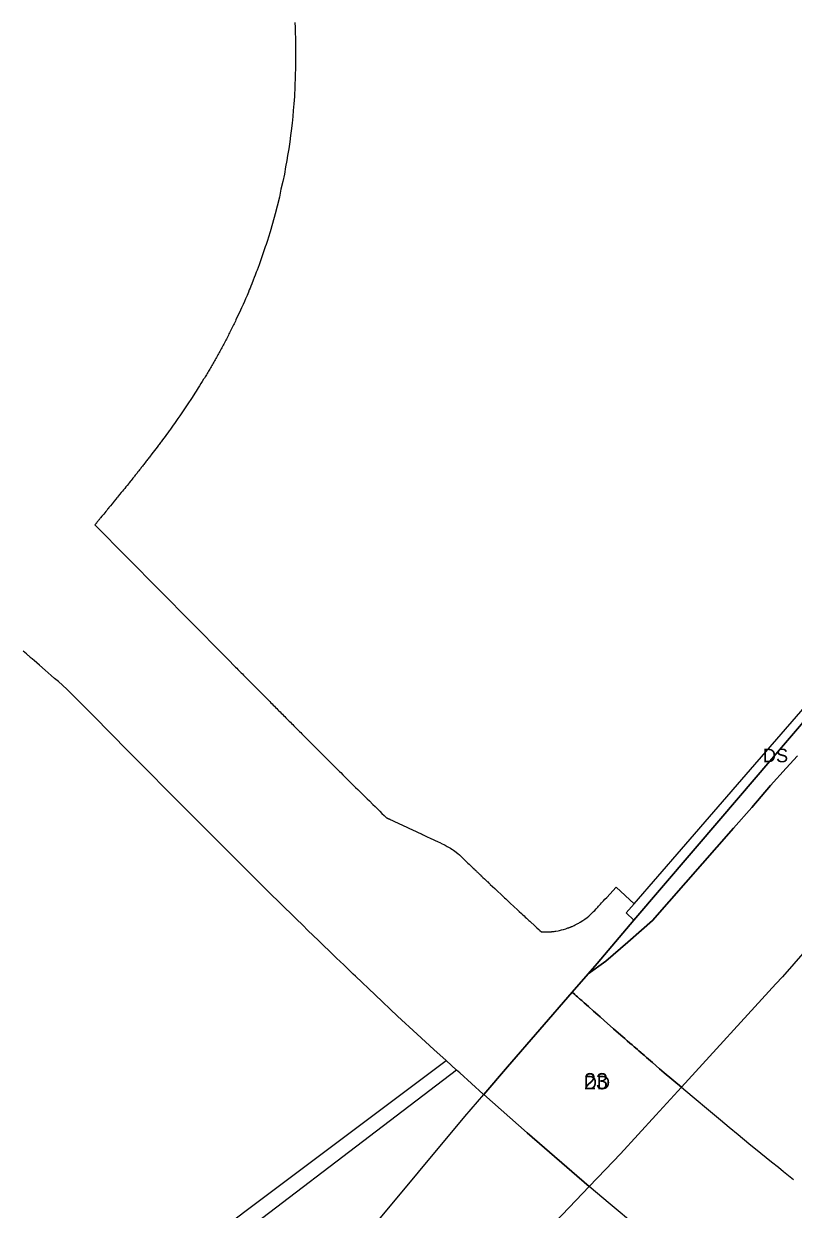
# Model space of a CAD drawing. Extents: x -537034 to -534353, y -1176562 to -1173176.
# Drawn here: x -536073.5 to -535789.3, y -1174862.1 to -1174424.3 of the extents above; entities that cross this region are included whole.
import ezdxf

# ---------------------------------------------------------------- set-up
doc = ezdxf.new("R2010")
doc.units = 0
for name, color, linetype in [('90320013', 7, 'Continuous'), ('90320023', 7, 'Continuous'), ('90330013', 7, 'Continuous'), ('90330023', 7, 'Continuous'), ('90390023', 7, 'Continuous'), ('ID_navrh', 7, 'Continuous')]:
    doc.layers.add(name, color=color, linetype=linetype)

msp = doc.modelspace()

# ---------------------------------------------------------------- linework, layer by layer
at = {"layer": '90320013'}
msp.add_lwpolyline([(-535848.15, -1174755.35), (-535850.97, -1174752.61), (-535848.1, -1174749.3), (-535830.53, -1174729.03), (-535805.04, -1174699.64), (-535782.42, -1174673.55), (-535753.14, -1174639.77), (-535750.85, -1174637.13), (-535749.98, -1174641.67), (-535765, -1174658.05), (-535771.01, -1174665.09), (-535791.35, -1174688.89), (-535816, -1174717.74)], close=True, dxfattribs=at)
msp.add_lwpolyline([(-536068.27, -1174920.24), (-535917.53, -1174807.16), (-535913.69, -1174810.62), (-536019.96, -1174891.69)], dxfattribs=at)
at = {"layer": '90320023'}
for points in [[(-535973.34, -1174423.76), (-535973.25, -1174425.67), (-535973.09, -1174431.51), (-535973.09, -1174440.09), (-535973.53, -1174451.08), (-535973.74, -1174453.87), (-535973.92, -1174456.32), (-535974.14, -1174458.55), (-535974.4, -1174460.96), (-535974.7, -1174463.8), (-535974.92, -1174465.59), (-535975.27, -1174467.86), (-535975.62, -1174470.51), (-535976.06, -1174472.91), (-535976.32, -1174474.79), (-535976.8, -1174477.15), (-535977.24, -1174479.82), (-535977.81, -1174482.49), (-535978.51, -1174485.37), (-535979.03, -1174488.26), (-535979.91, -1174491.58), (-535980.61, -1174494.47), (-535981.66, -1174498.05), (-535982.53, -1174501.11), (-535983.14, -1174503.12), (-535983.51, -1174504.29), (-535983.98, -1174505.75), (-535984.29, -1174506.7), (-535986.55, -1174513.28), (-535987.3, -1174515.29), (-535987.6, -1174516.05), (-535988.02, -1174517.16), (-535988.33, -1174518), (-535988.71, -1174518.94), (-535989.24, -1174520.28), (-535989.6, -1174521.18), (-535989.89, -1174521.88), (-535990.18, -1174522.58), (-535990.5, -1174523.37), (-535991.02, -1174524.56), (-535991.54, -1174525.8), (-535991.98, -1174526.78), (-535992.48, -1174527.97), (-535993.05, -1174529.17), (-535993.4, -1174530.02), (-535995.11, -1174533.63), (-535995.31, -1174534.06), (-535995.54, -1174534.54), (-535995.78, -1174535.02), (-535996.01, -1174535.51), (-535996.25, -1174535.98), (-535996.48, -1174536.46), (-535996.72, -1174536.94), (-535996.96, -1174537.41), (-535997.2, -1174537.89), (-535997.44, -1174538.36), (-535997.68, -1174538.83), (-535997.91, -1174539.3), (-535998.15, -1174539.76), (-535998.4, -1174540.23), (-535998.64, -1174540.69), (-535998.88, -1174541.16), (-535999.12, -1174541.62), (-535999.36, -1174542.08), (-535999.61, -1174542.53), (-535999.85, -1174542.99), (-536000.09, -1174543.44), (-536000.34, -1174543.89), (-536000.58, -1174544.35), (-536000.83, -1174544.8), (-536001.07, -1174545.24), (-536001.32, -1174545.69), (-536001.56, -1174546.13), (-536001.81, -1174546.58), (-536002.06, -1174547.02), (-536002.3, -1174547.46), (-536002.55, -1174547.9), (-536002.8, -1174548.33), (-536003.05, -1174548.77), (-536003.3, -1174549.2), (-536003.54, -1174549.64), (-536003.79, -1174550.07), (-536004.04, -1174550.49), (-536004.29, -1174550.92), (-536004.54, -1174551.35), (-536004.79, -1174551.77), (-536005.04, -1174552.2), (-536005.29, -1174552.62), (-536005.54, -1174553.04), (-536005.79, -1174553.46), (-536006.04, -1174553.87), (-536006.54, -1174554.7), (-536006.79, -1174555.12), (-536007.04, -1174555.53), (-536007.55, -1174556.35), (-536007.8, -1174556.75), (-536008.05, -1174557.16), (-536008.55, -1174557.96), (-536009.06, -1174558.76), (-536009.81, -1174559.95), (-536010.32, -1174560.74), (-536011.32, -1174562.29), (-536012.08, -1174563.45), (-536012.33, -1174563.83), (-536012.58, -1174564.21), (-536012.83, -1174564.58), (-536013.09, -1174564.96), (-536013.34, -1174565.34), (-536013.59, -1174565.71), (-536013.84, -1174566.08), (-536014.09, -1174566.45), (-536014.34, -1174566.82), (-536014.59, -1174567.19), (-536014.84, -1174567.56), (-536015.09, -1174567.93), (-536015.34, -1174568.29), (-536015.59, -1174568.65), (-536015.84, -1174569.02), (-536016.59, -1174570.09), (-536017.59, -1174571.51), (-536018.58, -1174572.91), (-536019.57, -1174574.29), (-536019.82, -1174574.63), (-536020.31, -1174575.3), (-536020.8, -1174575.98), (-536021.29, -1174576.65), (-536021.77, -1174577.31), (-536022.26, -1174577.97), (-536022.5, -1174578.29), (-536022.75, -1174578.62), (-536022.99, -1174578.95), (-536023.23, -1174579.27), (-536023.47, -1174579.59), (-536023.71, -1174579.91), (-536023.98, -1174580.27), (-536024.22, -1174580.59), (-536024.7, -1174581.22), (-536025.17, -1174581.85), (-536025.65, -1174582.48), (-536026.12, -1174583.09), (-536027.06, -1174584.32), (-536027.3, -1174584.62), (-536027.53, -1174584.92), (-536027.76, -1174585.22), (-536027.99, -1174585.52), (-536028.23, -1174585.82), (-536028.46, -1174586.12), (-536028.92, -1174586.71), (-536029.15, -1174587), (-536029.38, -1174587.3), (-536029.61, -1174587.59), (-536029.84, -1174587.88), (-536030.06, -1174588.17), (-536030.29, -1174588.46), (-536030.52, -1174588.75), (-536030.74, -1174589.03), (-536030.97, -1174589.32), (-536031.19, -1174589.6), (-536031.42, -1174589.88), (-536031.64, -1174590.17), (-536031.86, -1174590.45), (-536032.09, -1174590.73), (-536032.31, -1174591.01), (-536032.53, -1174591.28), (-536032.75, -1174591.56), (-536032.97, -1174591.84), (-536033.19, -1174592.11), (-536033.41, -1174592.38), (-536033.85, -1174592.93), (-536034.06, -1174593.2), (-536034.5, -1174593.74), (-536034.71, -1174594), (-536035.35, -1174594.8), (-536035.78, -1174595.32), (-536036.2, -1174595.85), (-536036.62, -1174596.36), (-536037.04, -1174596.88), (-536037.45, -1174597.39), (-536038.07, -1174598.14), (-536038.47, -1174598.64), (-536038.88, -1174599.14), (-536039.08, -1174599.38), (-536039.48, -1174599.87), (-536040.07, -1174600.6), (-536040.47, -1174601.08), (-536040.86, -1174601.56), (-536041.44, -1174602.27), (-536042.01, -1174602.96), (-536042.01, -1174602.97), (-536042.02, -1174602.97), (-536042.02, -1174602.98), (-536042.03, -1174602.99), (-536042.03, -1174603), (-536042.04, -1174603), (-536042.04, -1174603.01), (-536042.05, -1174603.01), (-536042.06, -1174603.02), (-536042.06, -1174603.03), (-536042.07, -1174603.04), (-536042.07, -1174603.05), (-536042.08, -1174603.06), (-536042.09, -1174603.07), (-536042.1, -1174603.08), (-536042.11, -1174603.09), (-536042.12, -1174603.1), (-536042.13, -1174603.11), (-536042.13, -1174603.12), (-536042.14, -1174603.12), (-536042.14, -1174603.13), (-536042.15, -1174603.13), (-536042.15, -1174603.14), (-536042.16, -1174603.15), (-536042.17, -1174603.16), (-536042.17, -1174603.17), (-536042.21, -1174603.21), (-536042.25, -1174603.26), (-536042.29, -1174603.31), (-536042.36, -1174603.39), (-536042.4, -1174603.44), (-536042.45, -1174603.5), (-536042.5, -1174603.56), (-536042.66, -1174603.75), (-536042.86, -1174604.01), (-536043.05, -1174604.23), (-536043.2, -1174604.41), (-536043.54, -1174604.84), (-536043.96, -1174605.35), (-536044.61, -1174606.14), (-536045.11, -1174606.76), (-536045.23, -1174606.9), (-536045.38, -1174607.08), (-536045.5, -1174607.23), (-536045.65, -1174607.41), (-536045.73, -1174607.51), (-536045.86, -1174607.66), (-536045.99, -1174607.83), (-536046.08, -1174607.94), (-536046.31, -1174608.21), (-536046.49, -1174608.44), (-536046.66, -1174608.64), (-536046.81, -1174608.83), (-536046.92, -1174608.96), (-536047.02, -1174609.09), (-536047.12, -1174609.21), (-536047.2, -1174609.3), (-536047.23, -1174609.35), (-535999.47, -1174657.57), (-535998.21, -1174658.84), (-535997.36, -1174659.7), (-535996.1, -1174660.98), (-535995.25, -1174661.83), (-535994.83, -1174662.25), (-535994.41, -1174662.68), (-535993.56, -1174663.53), (-535993.14, -1174663.96), (-535992.72, -1174664.38), (-535992.3, -1174664.81), (-535991.46, -1174665.66), (-535990.61, -1174666.51), (-535989.77, -1174667.36), (-535988.92, -1174668.21), (-535988.08, -1174669.06), (-535987.24, -1174669.91), (-535986.39, -1174670.77), (-535985.55, -1174671.62), (-535984.71, -1174672.47), (-535983.86, -1174673.32), (-535983.02, -1174674.17), (-535982.6, -1174674.59), (-535982.18, -1174675.01), (-535981.75, -1174675.44), (-535981.33, -1174675.86), (-535980.91, -1174676.29), (-535980.49, -1174676.71), (-535980.07, -1174677.14), (-535979.65, -1174677.56), (-535979.22, -1174677.99), (-535978.8, -1174678.41), (-535978.38, -1174678.83), (-535977.96, -1174679.26), (-535977.54, -1174679.68), (-535977.12, -1174680.11), (-535976.69, -1174680.53), (-535976.27, -1174680.95), (-535975.85, -1174681.38), (-535975.43, -1174681.8), (-535975.01, -1174682.23), (-535974.59, -1174682.65), (-535974.16, -1174683.07), (-535973.74, -1174683.5), (-535973.32, -1174683.92), (-535972.9, -1174684.34), (-535972.48, -1174684.77), (-535972.05, -1174685.19), (-535971.63, -1174685.61), (-535971.21, -1174686.04), (-535970.79, -1174686.46), (-535970.37, -1174686.88), (-535969.95, -1174687.31), (-535968.26, -1174689), (-535966.15, -1174691.11), (-535964.04, -1174693.22), (-535962.35, -1174694.91), (-535961.08, -1174696.17), (-535959.81, -1174697.43), (-535958.54, -1174698.7), (-535957.7, -1174699.54), (-535956.85, -1174700.38), (-535956.43, -1174700.8), (-535955.58, -1174701.64), (-535954.74, -1174702.48), (-535953.89, -1174703.32), (-535953.05, -1174704.16), (-535951.78, -1174705.42), (-535950.93, -1174706.25), (-535950.08, -1174707.09), (-535949.24, -1174707.93), (-535947.97, -1174709.19), (-535946.69, -1174710.44), (-535945.85, -1174711.28), (-535944.57, -1174712.53), (-535943.73, -1174713.36), (-535942.88, -1174714.2), (-535942.03, -1174715.03), (-535941.18, -1174715.87), (-535940.33, -1174716.7), (-535939.63, -1174717.38), (-535939.46, -1174717.47), (-535939.4, -1174717.49), (-535939.36, -1174717.51), (-535939.34, -1174717.52), (-535939.3, -1174717.54), (-535939.26, -1174717.56), (-535939.23, -1174717.57), (-535939.21, -1174717.58), (-535939.19, -1174717.59), (-535939.13, -1174717.62), (-535939.08, -1174717.64), (-535939.04, -1174717.66), (-535939.02, -1174717.67), (-535938.98, -1174717.69), (-535938.96, -1174717.7), (-535938.94, -1174717.71), (-535938.9, -1174717.73), (-535938.87, -1174717.74), (-535938.86, -1174717.75), (-535938.84, -1174717.75), (-535938.83, -1174717.76), (-535938.82, -1174717.76), (-535938.82, -1174717.77), (-535938.81, -1174717.77), (-535938.8, -1174717.77), (-535938.79, -1174717.78), (-535938.78, -1174717.78), (-535938.77, -1174717.79), (-535938.76, -1174717.79), (-535938.75, -1174717.8), (-535938.73, -1174717.81), (-535938.72, -1174717.81), (-535938.71, -1174717.82), (-535938.69, -1174717.82), (-535938.68, -1174717.83), (-535938.66, -1174717.84), (-535938.65, -1174717.84), (-535938.64, -1174717.85), (-535938.62, -1174717.86), (-535938.6, -1174717.87), (-535938.55, -1174717.89), (-535938.54, -1174717.9), (-535938.52, -1174717.9), (-535938.51, -1174717.91), (-535938.5, -1174717.91), (-535938.44, -1174717.94), (-535938.41, -1174717.96), (-535938.37, -1174717.98), (-535938.22, -1174718.04), (-535938.15, -1174718.08), (-535937.86, -1174718.21), (-535937.55, -1174718.36), (-535937.31, -1174718.47), (-535936.55, -1174718.83), (-535933.61, -1174720.2), (-535929.65, -1174722.06), (-535928.75, -1174722.48), (-535927.61, -1174723.01), (-535926.64, -1174723.47), (-535926.16, -1174723.69), (-535925.76, -1174723.88), (-535924.52, -1174724.47), (-535923.38, -1174725), (-535920.41, -1174726.38), (-535919.82, -1174726.66), (-535918.98, -1174727.06), (-535918.39, -1174727.35), (-535917.84, -1174727.62), (-535917.44, -1174727.85), (-535917.08, -1174728.04), (-535916.65, -1174728.29), (-535916.39, -1174728.44), (-535916.15, -1174728.59), (-535915.89, -1174728.76), (-535915.44, -1174729.05), (-535915.14, -1174729.25), (-535914.82, -1174729.47), (-535914.32, -1174729.83), (-535913.2, -1174730.67), (-535912.57, -1174731.22), (-535912.23, -1174731.52), (-535911.54, -1174732.14), (-535910.84, -1174732.83), (-535910.5, -1174733.2), (-535910.11, -1174733.61), (-535909.9, -1174733.82), (-535909.47, -1174734.22), (-535909.04, -1174734.63), (-535908.62, -1174735.04), (-535907.53, -1174736.06), (-535907.07, -1174736.51), (-535906.92, -1174736.65), (-535906.87, -1174736.69), (-535906.82, -1174736.74), (-535906.79, -1174736.77), (-535906.77, -1174736.79), (-535906.75, -1174736.81), (-535906.73, -1174736.82), (-535906.72, -1174736.83), (-535906.71, -1174736.84), (-535906.7, -1174736.85), (-535906.7, -1174736.86), (-535906.69, -1174736.86), (-535906.69, -1174736.87), (-535906.68, -1174736.87), (-535906.68, -1174736.88), (-535906.67, -1174736.88), (-535906.67, -1174736.89), (-535906.66, -1174736.89), (-535906.65, -1174736.9), (-535906.65, -1174736.91), (-535906.64, -1174736.91), (-535906.63, -1174736.92), (-535906.63, -1174736.93), (-535906.62, -1174736.93), (-535906.61, -1174736.94), (-535906.6, -1174736.95), (-535906.42, -1174737.13), (-535906.29, -1174737.24), (-535906.1, -1174737.42), (-535905.96, -1174737.56), (-535905.29, -1174738.19), (-535905.1, -1174738.37), (-535904.94, -1174738.52), (-535904.85, -1174738.61), (-535904.72, -1174738.73), (-535904.63, -1174738.82), (-535904.33, -1174739.1), (-535904.15, -1174739.27), (-535903.9, -1174739.5), (-535903.35, -1174740.03), (-535903.18, -1174740.18), (-535902.97, -1174740.39), (-535902.75, -1174740.59), (-535902.57, -1174740.76), (-535902.29, -1174741.02), (-535902.13, -1174741.17), (-535901.84, -1174741.45), (-535901.63, -1174741.64), (-535901.38, -1174741.88), (-535901.19, -1174742.07), (-535900.31, -1174742.88), (-535899.5, -1174743.65), (-535898.36, -1174744.72), (-535897.3, -1174745.7), (-535896.56, -1174746.4), (-535896.24, -1174746.7), (-535895.88, -1174747.03), (-535895.49, -1174747.41), (-535894.59, -1174748.23), (-535893.82, -1174748.97), (-535892.49, -1174750.2), (-535891.09, -1174751.53), (-535890.47, -1174752.07), (-535889.63, -1174752.86), (-535889.14, -1174753.31), (-535888.7, -1174753.71), (-535888.24, -1174754.13), (-535887.78, -1174754.56), (-535887.44, -1174754.88), (-535886.9, -1174755.36), (-535886.55, -1174755.7), (-535886.22, -1174756.01), (-535885, -1174757.13), (-535884.44, -1174757.64), (-535883.93, -1174758.09), (-535883.3, -1174758.71), (-535882.85, -1174759.1), (-535882.3, -1174759.61), (-535882.25, -1174759.61), (-535882.11, -1174759.62), (-535882.01, -1174759.62), (-535881.93, -1174759.62), (-535881.79, -1174759.63), (-535881.68, -1174759.63), (-535881.49, -1174759.64), (-535881.34, -1174759.64), (-535881.02, -1174759.64), (-535880.58, -1174759.64), (-535880.38, -1174759.64), (-535880.11, -1174759.63), (-535879.91, -1174759.62), (-535879.78, -1174759.62), (-535879.53, -1174759.6), (-535879.33, -1174759.59), (-535878.99, -1174759.57), (-535878.81, -1174759.55), (-535878.61, -1174759.54), (-535878.48, -1174759.52), (-535878.28, -1174759.5), (-535878.13, -1174759.49), (-535877.55, -1174759.42), (-535877.27, -1174759.38), (-535876.96, -1174759.33), (-535876.16, -1174759.19), (-535875.59, -1174759.07), (-535874.91, -1174758.91), (-535874.2, -1174758.72), (-535873.28, -1174758.46), (-535872.49, -1174758.17), (-535872.39, -1174758.14), (-535872.27, -1174758.1), (-535872.16, -1174758.06), (-535872.06, -1174758.02), (-535871.89, -1174757.95), (-535871.73, -1174757.89), (-535871.59, -1174757.83), (-535871.51, -1174757.8), (-535871.43, -1174757.77), (-535871.33, -1174757.73), (-535871.21, -1174757.68), (-535871.09, -1174757.63), (-535870.98, -1174757.58), (-535870.7, -1174757.46), (-535870.44, -1174757.34), (-535870.14, -1174757.2), (-535869.87, -1174757.07), (-535869.63, -1174756.94), (-535869.34, -1174756.8), (-535869.05, -1174756.64), (-535868.79, -1174756.5), (-535868.52, -1174756.34), (-535868.29, -1174756.21), (-535868.01, -1174756.05), (-535867.06, -1174755.45), (-535866.3, -1174754.9), (-535865.46, -1174754.29), (-535864.81, -1174753.76), (-535863.98, -1174753), (-535863.44, -1174752.51), (-535863.04, -1174752.11), (-535862.62, -1174751.67), (-535862.1, -1174751.12), (-535861.51, -1174750.48), (-535861.16, -1174750.1), (-535860.85, -1174749.75), (-535860.47, -1174749.35), (-535860.06, -1174748.91), (-535859.69, -1174748.52), (-535859.4, -1174748.2), (-535858.82, -1174747.58), (-535858.19, -1174746.9), (-535854.7, -1174743.15), (-535848.1, -1174749.3), (-535850.97, -1174752.61), (-535848.15, -1174755.35), (-535861.73, -1174771.25), (-535865.09, -1174775.14), (-535870.89, -1174781.85), (-535894.79, -1174809.5), (-535903.6, -1174819.7), (-535903.75, -1174819.57), (-535912.48, -1174811.71), (-535913.69, -1174810.62), (-535917.53, -1174807.16), (-535922, -1174803.02), (-535928.14, -1174797.34), (-535935.42, -1174790.71), (-535943.68, -1174782.86), (-535950.93, -1174776), (-535951.81, -1174775.17), (-535953.57, -1174773.49), (-535955.32, -1174771.81), (-535957.95, -1174769.29), (-535960.57, -1174766.76), (-535962.75, -1174764.66), (-535964.49, -1174762.97), (-535966.67, -1174760.86), (-535968.41, -1174759.17), (-535970.58, -1174757.06), (-535972.74, -1174754.94), (-535974.9, -1174752.82), (-535977.06, -1174750.7), (-535979.65, -1174748.16), (-535981.81, -1174746.04), (-535984.82, -1174743.06), (-535988.25, -1174739.66), (-535992.11, -1174735.83), (-535995.53, -1174732.43), (-535998.1, -1174729.87), (-536001.08, -1174726.88), (-536004.92, -1174723.05), (-536008.32, -1174719.63), (-536012.14, -1174715.79), (-536016.81, -1174711.1), (-536019.78, -1174708.11), (-536022.32, -1174705.55), (-536025.7, -1174702.13), (-536028.24, -1174699.57), (-536031.2, -1174696.59), (-536034.15, -1174693.6), (-536035, -1174692.75), (-536036.34, -1174691.4), (-536039.83, -1174687.87), (-536040.89, -1174686.79), (-536042.51, -1174685.18), (-536046.52, -1174681.11), (-536049.92, -1174677.67), (-536057.61, -1174669.95), (-536060.7, -1174667.21), (-536062.08, -1174666.04), (-536063.35, -1174664.93), (-536065.6, -1174662.99), (-536067.67, -1174661.17), (-536069.64, -1174659.45), (-536070.2, -1174658.96), (-536070.43, -1174658.76), (-536070.75, -1174658.48), (-536070.95, -1174658.3), (-536071.14, -1174658.14), (-536071.18, -1174658.11), (-536071.24, -1174658.05), (-536071.29, -1174658.01), (-536071.61, -1174657.73), (-536071.85, -1174657.52), (-536072.13, -1174657.28), (-536072.48, -1174656.97), (-536073.68, -1174655.94)], [(-535847.18, -1174868.32), (-535856.91, -1174860.12), (-535864.6, -1174853.66), (-535858.57, -1174847.35), (-535853.08, -1174841.6), (-535840.02, -1174827.31), (-535830.57, -1174816.98), (-535826.64, -1174820.33), (-535819.89, -1174825.91), (-535816.15, -1174829.08), (-535812.95, -1174831.73), (-535809.67, -1174834.47), (-535805.65, -1174837.7), (-535801.28, -1174841.34), (-535797.31, -1174844.54), (-535794.79, -1174846.56), (-535792.87, -1174848.11), (-535791.04, -1174849.58), (-535789.25, -1174851.01)]]:
    msp.add_lwpolyline(points, dxfattribs=at)
at = {"layer": '90330013'}
for points in [[(-535766.49, -1174745.54), (-535793.3, -1174776.23), (-535795.7, -1174778.85), (-535830.57, -1174816.98), (-535836.92, -1174811.61), (-535838.7, -1174810.13), (-535841.26, -1174807.87), (-535841.98, -1174807.25), (-535842.73, -1174806.61), (-535843.47, -1174805.95), (-535844.24, -1174805.31), (-535844.73, -1174804.89), (-535845.54, -1174804.17), (-535846.29, -1174803.56), (-535846.82, -1174803.06), (-535847.52, -1174802.47), (-535848.02, -1174802.03), (-535848.8, -1174801.34), (-535849.6, -1174800.66), (-535850.58, -1174799.81), (-535851.48, -1174799.01), (-535852.26, -1174798.32), (-535854.68, -1174796.22), (-535855.62, -1174795.41), (-535859.14, -1174792.31), (-535860.64, -1174791), (-535861.44, -1174790.28), (-535863.01, -1174788.9), (-535864.95, -1174787.17), (-535866.47, -1174785.82), (-535867.15, -1174785.21), (-535867.4, -1174785), (-535867.69, -1174784.73), (-535867.93, -1174784.53), (-535868.08, -1174784.39), (-535868.33, -1174784.17), (-535868.56, -1174783.97), (-535868.79, -1174783.76), (-535869.01, -1174783.56), (-535869.43, -1174783.18), (-535869.93, -1174782.74), (-535870.89, -1174781.85), (-535865.09, -1174775.14), (-535858.47, -1174770.38), (-535850.42, -1174763.36), (-535845.39, -1174758.98), (-535841.26, -1174755.38), (-535828.94, -1174741.37), (-535811.3, -1174721.31), (-535804.55, -1174713.65), (-535797.75, -1174705.59), (-535791.89, -1174699.19), (-535787.66, -1174694.59)], [(-535944.85, -1174868.93), (-535910.56, -1174827.75), (-535903.6, -1174819.7), (-535887.59, -1174833.85), (-535864.6, -1174853.66), (-535892.04, -1174882.37)]]:
    msp.add_lwpolyline(points, dxfattribs=at)
at = {"layer": '90330023'}
msp.add_lwpolyline([(-535870.89, -1174781.85), (-535869.93, -1174782.74), (-535869.43, -1174783.18), (-535869.01, -1174783.56), (-535868.79, -1174783.76), (-535868.56, -1174783.97), (-535868.33, -1174784.17), (-535868.08, -1174784.39), (-535867.93, -1174784.53), (-535867.69, -1174784.73), (-535867.4, -1174785), (-535867.15, -1174785.21), (-535866.47, -1174785.82), (-535864.95, -1174787.17), (-535863.01, -1174788.9), (-535861.44, -1174790.28), (-535860.64, -1174791), (-535859.14, -1174792.31), (-535855.62, -1174795.41), (-535854.68, -1174796.22), (-535852.26, -1174798.32), (-535851.48, -1174799.01), (-535850.58, -1174799.81), (-535849.6, -1174800.66), (-535848.8, -1174801.34), (-535848.02, -1174802.03), (-535847.52, -1174802.47), (-535846.82, -1174803.06), (-535846.29, -1174803.56), (-535845.54, -1174804.17), (-535844.73, -1174804.89), (-535844.24, -1174805.31), (-535843.47, -1174805.95), (-535842.73, -1174806.61), (-535841.98, -1174807.25), (-535841.26, -1174807.87), (-535838.7, -1174810.13), (-535836.92, -1174811.61), (-535830.57, -1174816.98), (-535840.02, -1174827.31), (-535853.08, -1174841.6), (-535858.57, -1174847.35), (-535864.6, -1174853.66), (-535887.59, -1174833.85), (-535903.6, -1174819.7), (-535894.79, -1174809.5)], close=True, dxfattribs=at)
at = {"layer": '90390023'}
msp.add_lwpolyline([(-535787.66, -1174694.59), (-535791.89, -1174699.19), (-535797.75, -1174705.59), (-535804.55, -1174713.65), (-535811.3, -1174721.31), (-535828.94, -1174741.37), (-535841.26, -1174755.38), (-535845.39, -1174758.98), (-535850.42, -1174763.36), (-535858.47, -1174770.38), (-535865.09, -1174775.14), (-535861.73, -1174771.25), (-535848.15, -1174755.35), (-535816, -1174717.74), (-535791.35, -1174688.89), (-535771.01, -1174665.09)], dxfattribs=at)

# ---------------------------------------------------------------- texts
at = {"layer": '90320013'}
msp.add_text('DS', height=5, rotation=0, dxfattribs=at).set_placement((-535800.48, -1174696.97))
at = {"layer": '90330023'}
msp.add_text('DD', height=5, rotation=360, dxfattribs=at).set_placement((-535866.6, -1174817.75))
at = {"layer": 'ID_navrh'}
msp.add_text('23', height=6, rotation=360, dxfattribs=at).set_placement((-535866.6, -1174817.75))

doc.saveas('drawing.dxf')
